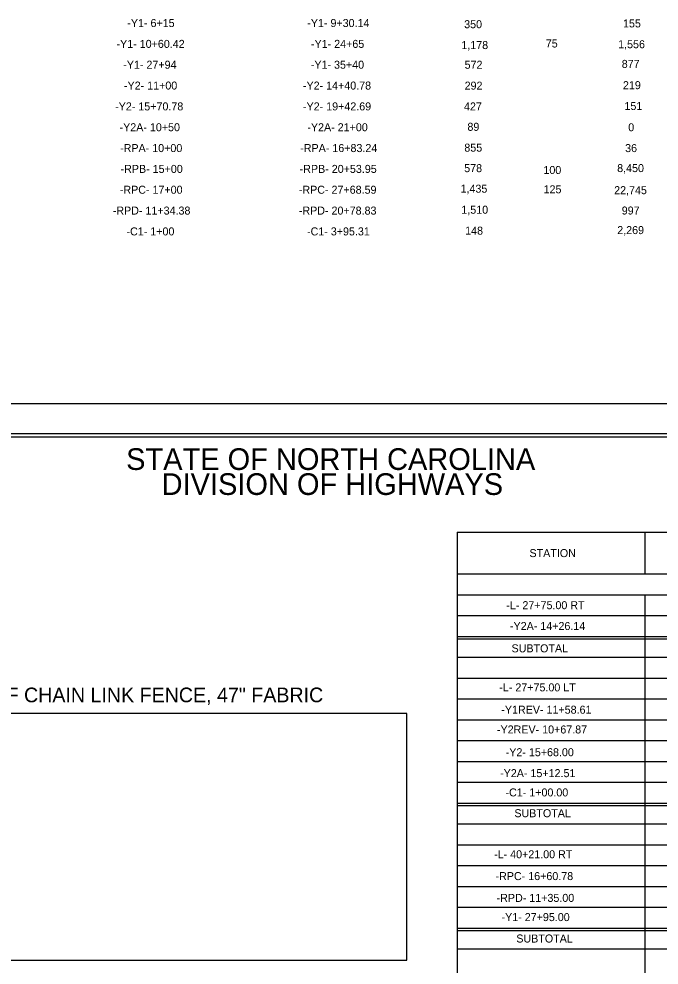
# Model space of a CAD drawing. Extents: x 573692 to 577281, y -53325 to -51406.
# Drawn here: x 574398 to 574877, y -52643 to -51934 of the extents above; entities that cross this region are included whole.
import ezdxf

# ---------------------------------------------------------------- set-up
doc = ezdxf.new("R2010")
doc.units = 0
for name, color, linetype in [('Exist Profile Cell', 7, 'Continuous'), ('Prop Conc Island Cover', 7, 'Continuous'), ('Prop EOT', 7, 'Continuous'), ('Sheet North Arrow CELL', 7, 'Continuous')]:
    doc.layers.add(name, color=color, linetype=linetype)

msp = doc.modelspace()

# ---------------------------------------------------------------- linework, layer by layer
at = {"layer": 'Exist Profile Cell'}
msp.add_lwpolyline([(575375.82, -52222.48), (573691.82, -52222.48), (573691.82, -53322.48), (575375.82, -53322.48)], close=True, dxfattribs=at)
at = {"layer": 'Prop Conc Island Cover'}
msp.add_lwpolyline([(575371.32, -52244.93), (573704.82, -52244.93), (573704.82, -53300.03), (575371.32, -53300.03)], close=True, dxfattribs=at)
at = {"layer": 'Prop EOT'}
msp.add_lwpolyline([(575358.82, -52247.48), (573858.82, -52247.48), (573858.82, -53297.48), (575358.82, -53297.48)], close=True, dxfattribs=at)
at = {"layer": 'Sheet North Arrow CELL'}
for p, q in [((574726, -52318.78), (575300.63, -52318.78)), ((574726, -52318.78), (574726, -52865.43)), ((574866.75, -52318.78), (574866.75, -52350.03)), ((574725.96, -52350.03), (575300.63, -52350.03)), ((574726, -52365.66), (575300.63, -52365.66)), ((574866.75, -52365.66), (574866.75, -52865.43)), ((574726, -52381.28), (575300.63, -52381.28)), ((574726, -52396.91), (575300.63, -52396.91)), ((574726, -52398.7), (575300.63, -52398.7)), ((574726, -52412.53), (575300.63, -52412.53)), ((574726, -52428.16), (575300.63, -52428.16)), ((574726, -52443.78), (575300.63, -52443.78)), ((574726, -52459.41), (575300.63, -52459.41)), ((574726, -52475.03), (575300.63, -52475.03)), ((574726, -52490.66), (575300.63, -52490.66)), ((574726, -52506.28), (575300.63, -52506.28)), ((574726, -52521.91), (575300.63, -52521.91)), ((574726, -52523.71), (575300.63, -52523.71)), ((574726, -52537.53), (575300.63, -52537.53)), ((574726, -52553.16), (575300.63, -52553.16)), ((574726, -52568.78), (575300.63, -52568.78)), ((574726, -52584.41), (575300.63, -52584.41)), ((574726, -52600.03), (575300.63, -52600.03)), ((574726, -52615.66), (575300.63, -52615.66)), ((574726, -52617.47), (575300.63, -52617.47)), ((574726, -52631.23), (575300.63, -52631.23))]:
    msp.add_line(p, q, dxfattribs=at)
msp.add_lwpolyline([(574297.1, -52639.78), (574688.33, -52639.78), (574688.33, -52454.76), (574297.1, -52454.76)], close=True, dxfattribs=at)

# ---------------------------------------------------------------- texts
at = {"layer": 'Prop EOT'}
for s, height, p in [('-Y1- 6+15', 6, (574478.8, -51939.93)), ('-Y1- 9+30.14', 6, (574613.69, -51939.93)), ('350', 6, (574731.29, -51940.81)), ('155', 6, (574850.37, -51940.21)), ('-Y1- 10+60.42', 6, (574470.71, -51955.56)), ('-Y1- 24+65', 6, (574616.48, -51955.56)), ('75', 6, (574792.47, -51955.26)), ('1,556', 6, (574846.71, -51955.83)), ('1,178', 6, (574729.18, -51956.44)), ('-Y1- 27+94', 6, (574475.76, -51971.18)), ('-Y1- 35+40', 6, (574616.36, -51971.18)), ('572', 6, (574731.62, -51971.19)), ('877', 6, (574849.39, -51970.58)), ('-Y2- 11+00', 6, (574476.31, -51986.81)), ('-Y2- 14+40.78', 6, (574610.44, -51986.81)), ('292', 6, (574731.62, -51986.86)), ('219', 6, (574850.3, -51986.52)), ('-Y2- 15+70.78', 6, (574469.67, -52002.43)), ('-Y2- 19+42.69', 6, (574610.48, -52002.43)), ('427', 6, (574731.16, -52002.49)), ('151', 6, (574851.43, -52002.15)), ('-Y2A- 10+50', 6, (574472.99, -52018.06)), ('-Y2A- 21+00', 6, (574613.76, -52018.06)), ('89', 6, (574733.72, -52017.74)), ('0', 6, (574854.27, -52018.09)), ('-RPA- 10+00', 6, (574473.4, -52033.68)), ('-RPA- 16+83.24', 6, (574608.41, -52033.68)), ('855', 6, (574731.41, -52033.37)), ('36', 6, (574851.92, -52033.71)), ('-RPB- 15+00', 6, (574473.74, -52049.31)), ('-RPB- 20+53.95', 6, (574607.98, -52049.31)), ('578', 6, (574731.3, -52048.75)), ('100', 6, (574790.69, -52050.14)), ('8,450', 6, (574845.97, -52048.7)), ('-RPC- 17+00', 6, (574473.18, -52064.93)), ('-RPC- 27+68.59', 6, (574607.35, -52064.93)), ('1,435', 6, (574728.57, -52064.14)), ('125', 6, (574790.81, -52064.61)), ('22,745', 6, (574843.72, -52065.27)), ('-RPD- 11+34.38', 6, (574467.89, -52080.56)), ('-RPD- 20+78.83', 6, (574607.35, -52080.56)), ('1,510', 6, (574729.17, -52079.92)), ('997', 6, (574849.39, -52080.52)), ('-C1- 1+00', 6, (574478.19, -52096.18)), ('-C1- 3+95.31', 6, (574613.5, -52096.18)), ('148', 6, (574732.02, -52095.62)), ('2,269', 6, (574846.02, -52095.2)), ('STATE OF NORTH CAROLINA', 16.2501, (574477.92, -52272.05)), ('DIVISION OF HIGHWAYS', 16.2501, (574504.52, -52290.8)), ('STATION', 6, (574780.25, -52337.41)), ('-L- 27+75.00 RT', 6, (574762.9, -52376.47)), ('-Y2A- 14+26.14', 6, (574765.62, -52392.1)), ('SUBTOTAL', 6, (574766.8, -52408.83)), ('-L- 27+75.00 LT', 6, (574757.62, -52438.1)), ('-Y1REV- 11+58.61', 6, (574759.13, -52454.84)), ('-Y2REV- 10+67.87', 6, (574755.86, -52469.67)), ('-Y2- 15+68.00', 6, (574762.41, -52486.72)), ('-Y2A- 15+12.51', 6, (574758.23, -52502.41)), ('-C1- 1+00.00', 6, (574762.25, -52516.87)), ('SUBTOTAL', 6, (574768.91, -52532.47)), ('-L- 40+21.00 RT', 6, (574753.73, -52563.25)), ('-RPC- 16+60.78', 6, (574754.78, -52579.61)), ('-RPD- 11+35.00', 6, (574755.58, -52595.97)), ('-Y1- 27+95.00', 6, (574759.3, -52610.36)), ('SUBTOTAL', 6, (574770.36, -52626.43))]:
    msp.add_text(s, height=height, dxfattribs=at).set_placement(p)
msp.add_text('SUMMARY OF CHAIN LINK FENCE, 47" FABRIC', height=11, rotation=0.01193, dxfattribs=at).set_placement((574297.6, -52446.31))

doc.saveas('drawing.dxf')
